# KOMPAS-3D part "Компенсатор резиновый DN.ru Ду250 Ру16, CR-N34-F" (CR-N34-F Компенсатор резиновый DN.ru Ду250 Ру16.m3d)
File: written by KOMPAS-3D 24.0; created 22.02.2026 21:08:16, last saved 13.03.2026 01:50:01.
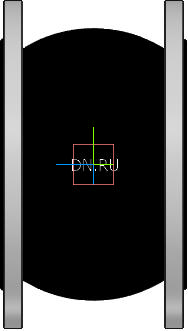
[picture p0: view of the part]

Document properties: Автор: DN.RU; Полное имя файла: CR-N34-F Компенсатор резиновый DN.ru Ду250 Ру16.cdw

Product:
- Body: Твердое тело2  | qty 1
    Масса: 70.952857
- Part/product: Компенсатор резиновый DN.ru Ду250 Ру16  | designation CR-N34-F
    Масса: 25
    Раздел спецификации: Прочие изделия
    Форматы листов документа: A2
    Комментарий: D140-02108
    Примечание: D140-02108
    additional columns: Типовые

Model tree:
1. Твердое тело2  (labels: Твердое тело2)

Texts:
  CR-N34-F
